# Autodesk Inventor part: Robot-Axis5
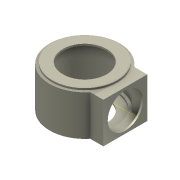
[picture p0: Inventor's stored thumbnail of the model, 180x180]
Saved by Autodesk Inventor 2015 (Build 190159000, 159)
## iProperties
Shininess: 21.0
Length Units: 11269
Angle Units: 11279
Time Units: 11290
Mass Units: 11283
Length Display Precision: 3
Angle Display Precision: 2
Created: 2001-08
Part Number: Robot-Axis5
Document SubType Name: ﾓﾃﾞﾘﾝｸﾞ
Designer: Administrator
Density: 1 g/cm^3
Material: Generic
Appearance: Smooth - Ivory
Density: 0.0
Volumn: 0.0
Area: 0.0
PropertySet Name: Model Information
Control State: 0
Master: False
Checked Out: False
Author: Administrator
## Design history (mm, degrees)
sketch "ｽｹｯﾁ1"
  geometry: C1 r 40 at (0, 0)
  constraints: 1 centre point
  dimensions: "d0" = 80 diameter of C1
extrude "押し出し1" new body sketch "ｽｹｯﾁ1" taper "d2" = 0 deg
sketch "ｽｹｯﾁ2"
  geometry: C1 r 40 at (0, 0) reference; C2 r 37 at (0, 0)
  constraints: 1 centre point
  dimensions: "d3" = 3 radial gap between concentric circles of C1 C2
extrude "押し出し2" join sketch "ｽｹｯﾁ2" distance "d4" = 2; taper "d5" = 0 deg
node "作業平面1"
sketch "ｽｹｯﾁ3"
  geometry: L1 (-37, -25)-(37, -25) reference; L2 (40, -23)-(-40, -23) reference; L3 (-25, 23)-(25, 23); L4 (25, 23)-(25, -23); L5 (25, -23)-(-25, -23); L6 (-25, -23)-(-25, 23); L7 (-25, 0)-(25, 0); L8 (0, 23)-(0, -23); L9 (0, -23)-(0, 24.715)
  constraints: 14 end point, 6 midpoint, 2 collinear, 2 parallel, 2 perpendicular, 1 horizontal, 1 point on line
  dimensions: "d6" = 50 distance of L3.start L3.end; "d7" = 46 distance of L5.end L3.start; "d8" = 25 distance between parallel lines of L6 L8
extrude "押し出し3" join sketch "ｽｹｯﾁ3" distance "d9" = 46.2; taper "d10" = 0 deg
node "作業軸1"
workaxis "Work Axis2"
  workplane "Work Plane2"
  workplane "Work Plane3"
shell "Shell1" dims "d20" = 2
sketch "Sketch7"
  geometry: C1 r 37 at (0, 0) reference
hole "Hole1" sketch "Sketch7" at (0, 0) diameter "d21" = 50; stored, may be unused: countersink angle "d25" = 82 deg, drill point angle "d27" = 118 deg; dims "d22" = 6, "d23" = 4, "d24" = 2, "d26" = 8
sketch "Sketch8"
  geometry: 1 further point
hole "Hole2" sketch "Sketch8" at (0, 0) diameter "d28" = 40; stored, may be unused: countersink angle "d32" = 82 deg, drill point angle "d34" = 118 deg; dims "d29" = 6, "d30" = 4, "d31" = 2, "d33" = 2
body "Solid1"
mirror "Mirror1"
sketch "Sketch4"
  geometry: 1 further point
